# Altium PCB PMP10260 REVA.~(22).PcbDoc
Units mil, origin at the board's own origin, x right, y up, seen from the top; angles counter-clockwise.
Board outline 5118.11 x 4724.41 mil, 4 copper layers (Top Layer, MidLayer1, MidLayer2, Bottom Layer), stack 63.8 mil thick; 168 components, 80 nets, 422 pads, 195 vias.
Unrouted connection lines stored in the file: 320.
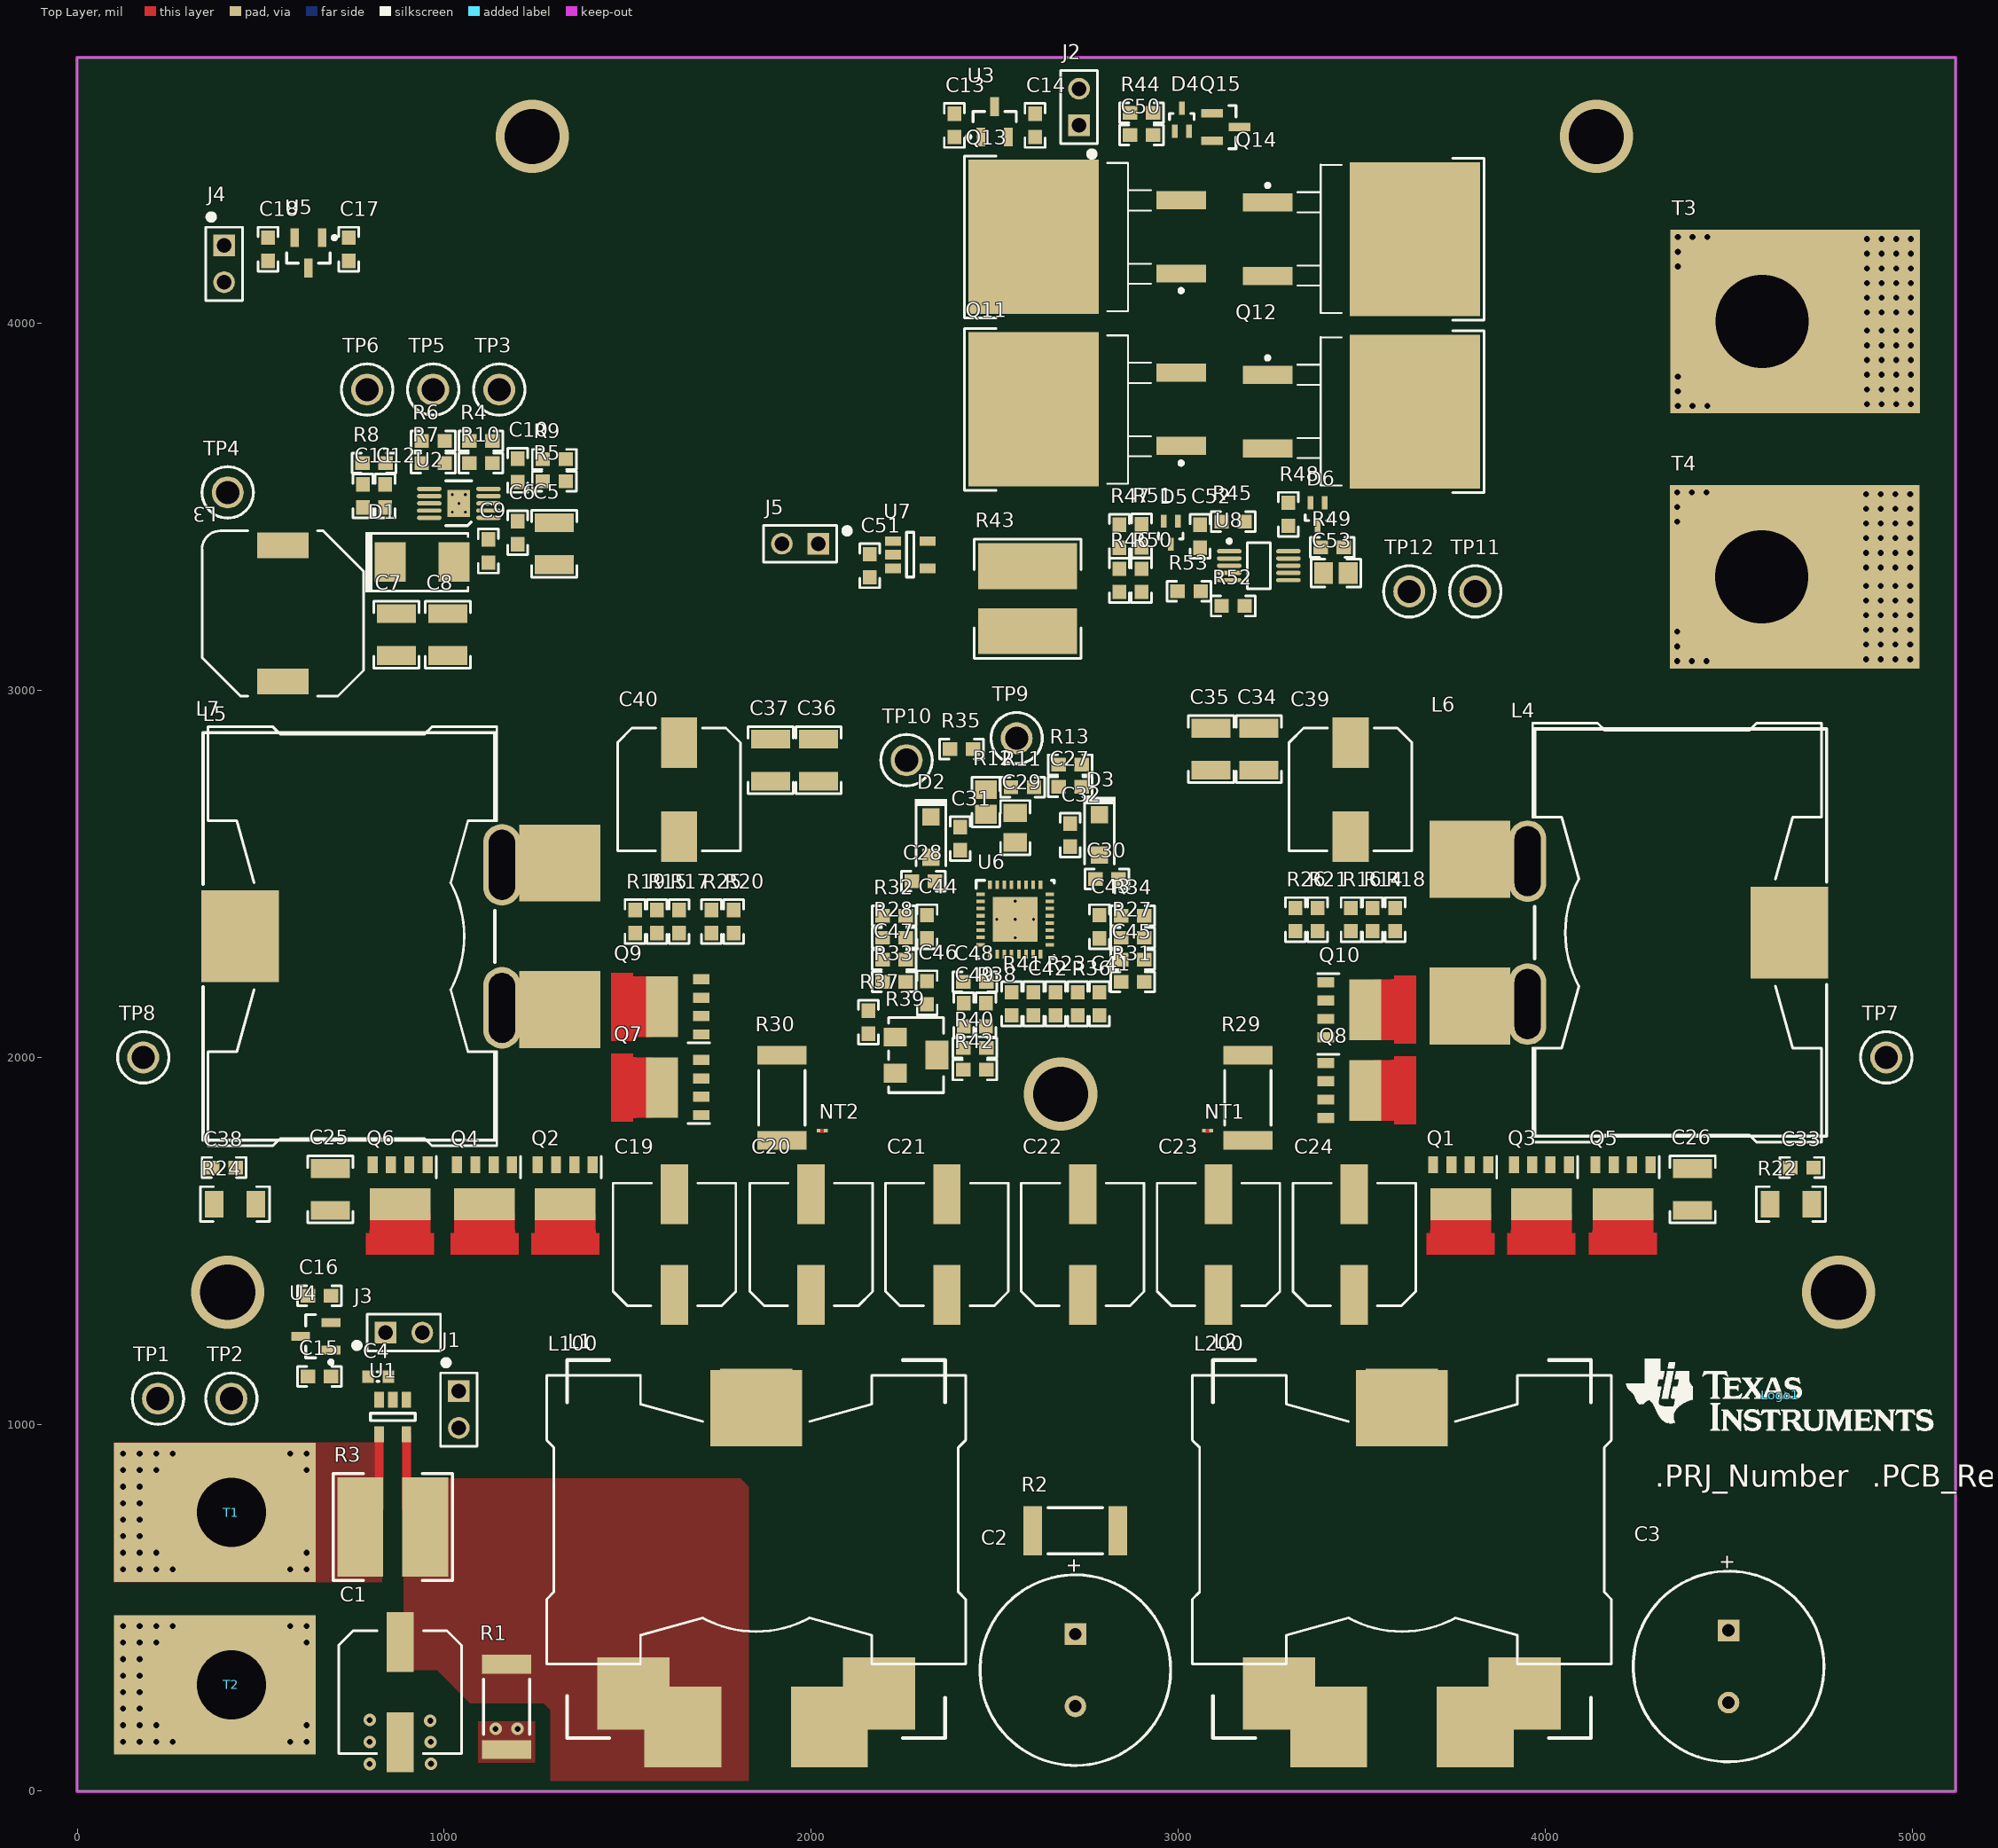
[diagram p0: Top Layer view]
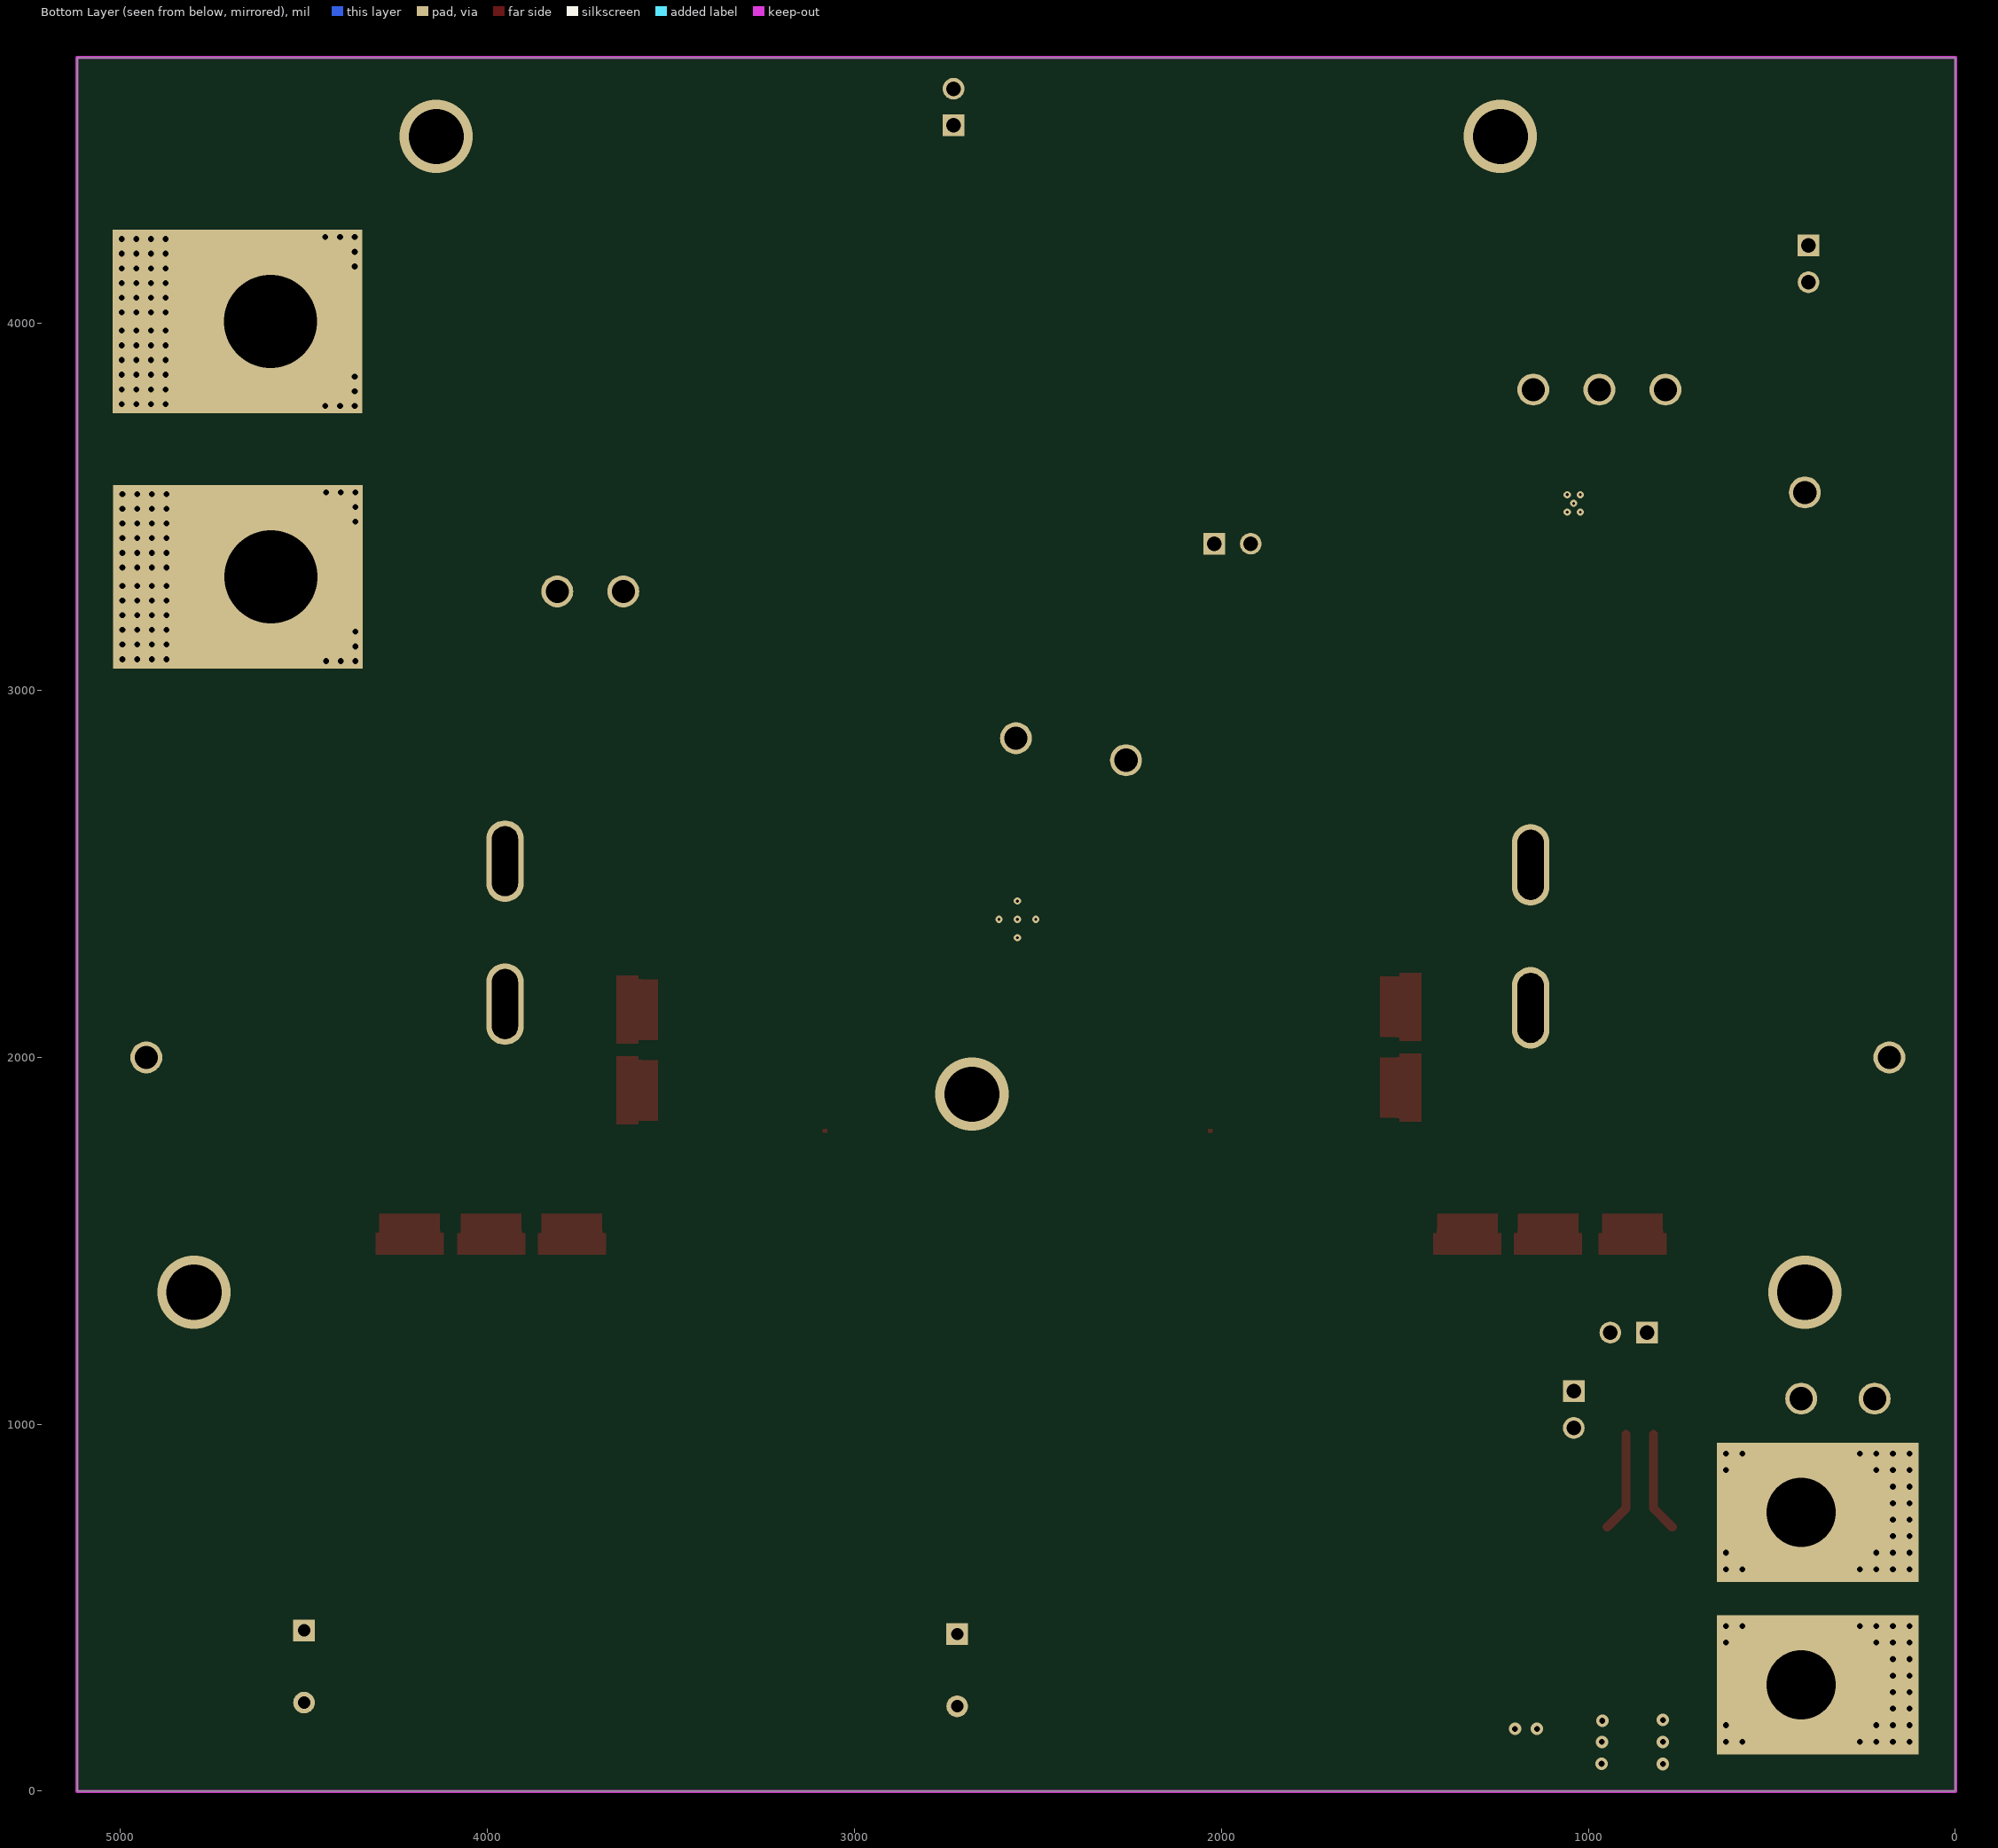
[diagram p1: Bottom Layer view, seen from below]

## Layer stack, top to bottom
Top Layer: signal copper 2.8
Dielectric: core 20, FR-4, Dk 4.8
MidLayer1: signal copper 2.8
Dielectric: prepreg 12.6, FR-4, Dk 4.8
MidLayer2: signal copper 2.8
Dielectric: core 20, FR-4, Dk 4.8
Bottom Layer: signal copper 2.8

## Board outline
0,0 5118.11,0 5118.11,4724.41 0,4724.41

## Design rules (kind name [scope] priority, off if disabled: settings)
AcuteAngle [All] p1: minimum=4.50000000000000E+0001 checktracksonly=FALSE
AssemblyTestPointUsage [All] p1: valid=2
Clearance Clearance_BoardEdge_MountingHoles [OnCopper and InComponentClass('Mounting Holes') vs IsKeepOut] p1: gap=40
Clearance Clearance_BoardEdge_Poly [OnCopper and InPoly vs IsKeepOut] p2: gap=25
Clearance Clearance_BoardEdge [OnCopper and Not InComponentClass('Logo') and not InComponentClass('FiducialMark') and not InRegion(1000,500,4000,800) and Not IsKeepout vs IsKeepOut] p3: gap=25
Clearance Clearance_Poly [InPolygon] p4: gap=15
Clearance [All] p5: gap=8
ComponentClearance ComponentClearance_Shunt [InComponentClass('Header') vs InComponentClass('Shunt')] p1: gap=0 collisioncheckmode=3 verticalgap=0 showdistances=FALSE
ComponentClearance ComponentClearance_Logo [InComponentClass('Logo')] p2: gap=20 collisioncheckmode=3 verticalgap=10 showdistances=FALSE
ComponentClearance ComponentClearance_ScrewToNut [(HasFootprint('NY PMS 440 0025 PH')) vs (HasFootprint('Keystone_1902C'))] p3: gap=5 collisioncheckmode=3 verticalgap=10 showdistances=FALSE
ComponentClearance ComponentClearance_MountingHoles [InComponentClass('Mounting Holes')] p4: gap=100 collisioncheckmode=3 verticalgap=100000 showdistances=FALSE
ComponentClearance ComponentClearance_SmallPassives [HasFootprint('0201*') or HasFootprint('0402*') or HasFootprint('0508') or HasFootprint('0603*') or HasFootprint('0612') or HasFootprint('0805*') or HasFootprint('0815*') or HasFootprint('0830*') or HasFootprint('1206*') or HasFootprint('1210*') or HasFootprint('1808*') or HasFootprint('1812*') or HasFootprint('1825*') or HasFootprint('2010*') or HasFootprint('2220*') or HasFootprint('2225*') or HasFootprint('2512*') or HasFootprint('2728*') or HasFootprint('3518*') vs HasFootprint('0201*') or HasFootprint('0402*') or HasFootprint('0508') or HasFootprint('0603*') or HasFootprint('0612') or HasFootprint('0805*') or HasFootprint('0815*') or HasFootprint('0830*') or HasFootprint('1206*') or HasFootprint('1210*') or HasFootprint('1808*') or HasFootprint('1812*') or HasFootprint('1825*') or HasFootprint('2010*') or HasFootprint('2220*') or HasFootprint('2225*') or HasFootprint('2512*') or HasFootprint('2728*') or HasFootprint('3518*')] p5: gap=15 collisioncheckmode=3 verticalgap=10 showdistances=FALSE
ComponentClearance ComponentClearance_THtoSMT [IsThruComponent vs IsSMTComponent] p6: gap=50 collisioncheckmode=3 verticalgap=30 showdistances=FALSE
ComponentClearance ComponentClearance_THtoTH [IsThruComponent vs IsThruComponent] p7: gap=50 collisioncheckmode=3 verticalgap=30 showdistances=FALSE
ComponentClearance [All] p8: gap=25 collisioncheckmode=3 verticalgap=10 showdistances=FALSE
DiffPairsRouting [All] p1: maxlimit=100 minlimit=10 mostfreqgap=10 maxuncoupledlength=1000
FabricationTestPointUsage TestPointUsage [All] p1: valid=2 allowmultiple=FALSE
FabricationTestpoint Testpoint [All] p1: side=3 testpointundercomponent=TRUE minsize=40 maxsize=100 preferedsize=60 minholesize=0 maxholesize=40 preferedholesize=32 testpointgrid=1 allowsidetop=TRUE allowsidebottom=TRUE usegrid=TRUE gridtolerance=0.01
FanoutControl Fanout_LCC [IsLCC] p1: bgadir=Out bgaviamode=Centered fanoutstyle=Auto fanoutdirection=Alternating viagrid=1 // Fanout_LCC (Default Rule)
FanoutControl Fanout_BGA [IsBGA] p2: bgadir=Out bgaviamode=Centered fanoutstyle=Auto fanoutdirection=Alternating viagrid=1 // Fanout_BGA (Default Rule)
FanoutControl Fanout_Default [All] p4: bgadir=Out bgaviamode=Centered fanoutstyle=Auto fanoutdirection=Alternating viagrid=1 // Fanout_Default (Default Rule)
FanoutControl Fanout_Small [(CompPinCount < 5)] p5: bgadir=Out bgaviamode=Centered fanoutstyle=Auto fanoutdirection=OutThenIn viagrid=1 // Fanout_Small (Default Rule)
HoleSize [All] p1: absolutevalues=TRUE maxlimit=251 minlimit=8 maxpercent=80.000 minpercent=20.000
MinimumAnnularRing MinimumAnnularRing_ThermalPadVias [IsVia and InAnyComponent] p1: minimumring=5.91
MinimumAnnularRing [All] p2: minimumring=9
MinimumSolderMaskSliver MinimumSolderMaskSliver_Logo [InComponentClass('Logo') vs InComponentClass('Logo')] p1: minsoldermaskwidth=0.7
MinimumSolderMaskSliver [All] p2: minsoldermaskwidth=3
PlaneClearance [All] p1: clearance=15
PlaneConnect [All] p1: planeconnectstyle=Direct reliefexpansion=10 reliefentries=4 reliefconductorwidth=10 reliefairgap=10
PolygonConnect [All] p1: connectstyle=Direct reliefconductorwidth=10 reliefentries=4 polygonreliefangle="90 Angle" airgapwidth=10
RoomDefinition "PMP10260 REVA SH3" [InComponentClass('PMP10260 REVA SH3')] p1: confinementstyle=ConfineIn formatcopy=TRUE lockcomponents=FALSE outline -692,-1534 1308,-1534 1308,-534 -692,-534
RoomDefinition "PMP10260 REVA SH2" [InComponentClass('PMP10260 REVA SH2')] p2: confinementstyle=ConfineIn formatcopy=TRUE lockcomponents=FALSE outline -692,-1534 1308,-1534 1308,-534 -692,-534
RoutingVias ThermalPadVias [IsVia and InAnyComponent] p1: holewidth=7.87 width=19.68 viastyle="Through Hole" minholewidth=7.87 minwidth=19.68 maxholewidth=12.99 maxwidth=23.62
RoutingVias [All] p2: holewidth=16 width=34 viastyle="Through Hole" minholewidth=7.87 minwidth=26 maxholewidth=40 maxwidth=65
SMDToCorner [All] p1: distance=30000
SilkToSilkClearance [All] p1: silktosilkclearance=0
SilkscreenOverComponentPads [All] p1: minsilkscreentomaskgap=0
SolderMaskExpansion [All] p1: expansion=1.97
Width [All] p1: maxlimit=100 minlimit=6 preferedwidth=10 checkconnectedcopper=TRUE
13 further rules are at their usual default settings.

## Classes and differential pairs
component class Logo: Logo1
component class Header: J1 J2 J3 J4 J5
component class "PMP10260 REVA SH1": C1 C2 C3 C4 C5 C6 C7 C8 C9 C10 C11 C12 C13 C14 C15 C16 C17 C18 D1 J1 J2 J3 J4 L1 L2 L3 L100 L200 Logo1 R1 R2 R3 R4 R5 R6 R7 R8 R9 R10 T1 T2 TP1 TP2 TP3 TP4 TP5 TP6 U1 U2 U3 U4 U5
component class "PMP10260 REVA SH2": C19 C20 C21 C22 C23 C24 C25 C26 C27 C28 C29 C30 C31 C32 C33 C34 C35 C36 C37 C38 C39 C40 C41 C42 C43 C44 C45 C46 C47 C48 C49 D2 D3 L4 L5 L6 L7 NT1 NT2 Q1 Q2 Q3 Q4 Q5 Q6 Q7 Q8 Q9 Q10 R11 R12 R13 R14 R15 R16 R17 R18 R19 R20 R21 R22 R23 R24 R25 R26 R27 R28 R29 R30 R31 R32 R33 R34 R35 R36 R37 R38 R39 R40 R41 R42 TP7 TP8 TP9 TP10 U6
component class "PMP10260 REVA SH3": C50 C51 C52 C53 D4 D5 D6 J5 Q11 Q12 Q13 Q14 Q15 R43 R44 R45 R46 R47 R48 R49 R50 R51 R52 R53 T3 T4 TP11 TP12 U7 U8

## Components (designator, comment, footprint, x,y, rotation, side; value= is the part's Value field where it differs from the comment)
C1 "63SXV33M" SXV_E12 880,270 r270 top
C2 "63ZLH470M12.5X25" ZLH_1250x2500 2720,330 r270 top
C3 "63ZLH470M12.5X25" ZLH_1250x2500 4500,340 r270 top
C4 "C1608X7R1H104K" 0603L 820,1130 r0 top
C5 "GRM32ER72A225KA35L" 1210 1300.02,3399.97 r270 top
C6 "GRM188R72A104KA35D" 0603 1200.02,3429.97 r270 top
C7 "C3225X7R1C226M" 1210 869.7,3152.41 r90 top
C8 "C3225X7R1C226M" 1210 1009.7,3152.41 r90 top
C9 "C1608X7R1H104K" 0603 1120.02,3379.97 r90 top
C10 "C1608X7R1H103K" 0603 1200.02,3599.97 r90 top
C11 "C1608C0G1H472J" 0603 778.56,3529.97 r270 top
C12 "" 0603 838.56,3529.97 r270 top
C13 "C1608X7R1H104K" 0603 2390,4540 r90 top
C14 "C1608X7R1E105K080AB" 0603 2610,4540 r90 top
C15 "C1608X7R1H104K" 0603 660,1130 r180 top
C16 "C1608X7R1E105K080AB" 0603 660,1350 r180 top
C17 "C1608X7R1H104K" 0603 740,4202.44 r270 top
C18 "C1608X7R1E105K080AB" 0603 520,4202.44 r270 top
C19 "63SXV33M" SXV_E12 1627.32,1490 r90 top
C20 "63SXV33M" SXV_E12 2000,1490 r90 top
C21 "63SXV33M" SXV_E12 2370,1490 r90 top
C22 "63SXV33M" SXV_E12 2740,1490 r90 top
C23 "63SXV33M" SXV_E12 3110,1490 r90 top
C24 "63SXV33M" SXV_E12 3480,1490 r90 top
C25 "GRM32ER72A225KA35L" 1210 690,1640 r90 top
C26 "GRM32ER72A225KA35L" 1210 4402.28,1640.16 r90 top
C27 "C1608C0G1H471J" 0603 2706.06,2737.36 r0 top
C28 "C1608X7R1E105K080AB" 0603 2306.06,2480.51 r180 top
C29 "C2012X7R2A104K" 0805_HV 2556.06,2626.06 r90 top
C30 "C1608X7R1E105K080AB" 0603 2806.06,2486.06 r0 top
C31 "C1608X7R1E105K080AB" 0603 2406.06,2596.06 r270 top
C32 "C1608X7R1E105K080AB" 0603 2706.06,2606.06 r270 top
C33 "C0603C222K5RAC" 0603 4700,1700 r0 top
C34 "GMK325AB7106MM-T" 1210 3220,2840 r270 top
C35 "" 1210 3090,2840 r270 top
C36 "" 1210 2020,2810 r270 top
C37 "GMK325AB7106MM-T" 1210 1890,2810 r270 top
C38 "C0603C222K5RAC" 0603 400,1700 r180 top
C39 "20SVPF390M" SM_RADIAL_8MM 3470,2730 r270 top
C40 "20SVPF390M" SM_RADIAL_8MM 1640,2730 r270 top
C41 "C1608X7R1H104K" 0603 2786.06,2146.06 r90 top
C42 "C0603C474K4RACTU" 0603 2606.06,2146.06 r90 top
C43 "C1608C0G1H102J" 0603 2786.06,2356.06 r90 top
C44 "C1608C0G1H102J" 0603 2316.06,2356.06 r90 top
C45 "C1608C0G1H102J" 0603 2876.06,2266.06 r0 top
C46 "C1608X7R1H104K" 0603 2316.06,2176.06 r270 top
C47 "C1608C0G1H102J" 0603 2226.06,2266.06 r180 top
C48 "C1608C0G1H101J" 0603 2446.06,2206.06 r180 top
C49 "GRM188R71H333KA61D" 0603 2416.06,2116.06 r90 top
C50 "C1608X7R1H103K" 0603 2900.2,4514.07 r180 top
C51 "C1608X7R1H104K" 0603 2160,3340 r90 top
C52 "C1608X7R1H104K" 0603 3060,3420 r90 top
C53 "0805YC274KAT2A" 0805 3430,3320 r0 top
D1 "MBRS1100T3G" SMB 940.02,3349.97 r0 top
D2 "PMEG6010CEH" SOD-123F 2326.06,2600.51 r270 top
D3 "PMEG6010CEH" SOD-123F 2786.06,2606.06 r270 top
D4 "BAS116T-7-F" SOT-523 3010.2,4555.39 r90 top
D5 "BAS116T-7-F" SOT-523 2980,3430 r270 top
D6 "BAS116T-7-F" SOT-523 3380,3480 r270 top
J1 "PEC02SAAN" CONN_PEC02SAAN 1040,1040 r270 top
J2 "PEC02SAAN" CONN_PEC02SAAN 2730,4590 r90 top
J3 "PEC02SAAN" CONN_PEC02SAAN 890,1250 r0 top
J4 "PEC02SAAN" CONN_PEC02SAAN 400,4162.44 r270 top
J5 "PEC02SAAN" CONN_PEC02SAAN 1970,3400 r180 top
L1 "PG1096.152NL" IND_PG1096 1850,660 r0 top
L2 "PG1096.152NL" IND_PG1096 3610,660 r0 top
L3 "MSS1048-104MLB" MSS1048 560.02,3209.97 r270 top
L4 "" SER29XX 4330,2340 r90 top
L5 "" SER29XX 779.84,2330 r270 top
L6 "SER2915H-682KL" SER2915 4360,2340 r0 top
L7 "SER2915H-682KL" SER2915 749.84,2330 r180 top
L100 "" SER2918 1850,740 r90 top
L200 "" SER2918 3610,740 r90 top
Logo1 "Texas Instruments" TI_Stacked_Overlay_Small 4640,1080 r0 top
NT1 "Net-Tie" Net-Tie_10mil 3080,1800 r0 top net-tie
NT2 "Net-Tie" Net-Tie_10mil 2030,1800 r0 top net-tie
Q1 "BUK7Y6R0-60EX" LFPAK56 3770,1600 r180 top
Q2 "BUK7Y6R0-60EX" LFPAK56 1329.84,1600 r180 top
Q3 "BUK7Y6R0-60EX" LFPAK56 3990,1600 r180 top
Q4 "BUK7Y6R0-60EX" LFPAK56 1109.84,1600 r180 top
Q5 "BUK7Y6R0-60EX" LFPAK56 4212.28,1600.16 r180 top
Q6 "BUK7Y6R0-60EX" LFPAK56 879.84,1600 r180 top
Q7 "BUK7Y6R0-60EX" LFPAK56 1593.46,1917.72 r90 top
Q8 "BUK7Y6R0-60EX" LFPAK56 3510,1910 r270 top
Q9 "BUK7Y6R0-60EX" LFPAK56 1593.46,2137.72 r90 top
Q10 "BUK7Y6R0-60EX" LFPAK56 3510,2130 r270 top
Q11 "IPB120N04S4-02" DDPAK 2762.09,3766.18 r180 top
Q12 "IPB120N04S4-02" DDPAK 3490,3760 r0 top
Q13 "IPB120N04S4-02" DDPAK 2762.09,4236.18 r180 top
Q14 "IPB120N04S4-02" DDPAK 3490,4230 r0 top
Q15 "MMBT2222A" SOT-23 3130.2,4535.39 r0 top
R1 "CSRN2512FKR200" 2512 1170,230 r270 top
R2 "CSRN2512FKR200" 2512 2720,710 r0 top
R3 "CSS2725FT1L00" CSS2725_0005 860,720 r0 top
R4 "CRCW060349R9FKEA" 0603 1100,3680 r0 top
R5 "CRCW0603178KFKEA" 0603 1300.02,3569.97 r0 top
R6 "CRCW060353K6FKEA" 0603 970.02,3679.65 r0 top
R7 "CRCW060310K2FKEA" 0603 970.02,3619.97 r180 top
R8 "CRCW060388K7FKEA" 0603 808.56,3619.97 r180 top
R9 "CRCW060349K9FKEA" 0603 1300.02,3629.97 r180 top
R10 "CRCW0603237KFKEA" 0603 1100.02,3619.97 r0 top
R11 "CRCW060375K0FKEA" 0603 2576.06,2736.06 r180 top
R12 "CRCW08051R00FKEA" 0805 2476.06,2696.06 r270 top
R13 "CRCW06035K76FKEA" 0603 2706.06,2797.36 r180 top
R14 "CRCW06032R20JNEA" 0603 3530,2375.55 r270 top
R15 "CRCW06032R20JNEA" 0603 1580,2370 r90 top
R16 "CRCW06032R20JNEA" 0603 3471.3,2375.55 r270 top
R17 "CRCW06032R20JNEA" 0603 1640,2370 r90 top
R18 "CRCW06032R20JNEA" 0603 3591.3,2375.55 r270 top
R19 "CRCW06032R20JNEA" 0603 1520,2370 r90 top
R20 "CRCW06032R20JNEA" 0603 1788.7,2370 r90 top
R21 "CRCW06032R20JNEA" 0603 3380,2375.55 r270 top
R22 "CRCW120610R0JNEA" 1206 4670,1600 r0 top
R23 "CRCW06030000Z0EA" 0603 2666.06,2146.06 r270 top
R24 "CRCW120610R0JNEA" 1206 430,1600 r180 top
R25 "CRCW06032R20JNEA" 0603 1728.7,2370 r90 top
R26 "CRCW06032R20JNEA" 0603 3320,2375.55 r270 top
R27 "RC0603FR-07100RL" 0603 2876.06,2326.06 r0 top
R28 "RC0603FR-07100RL" 0603 2226.06,2326.06 r180 top
R29 "ERJ-M1WTF1M0U" 2512 3190,1890 r90 top
R30 "ERJ-M1WTF1M0U" 2512 1920,1890 r90 top
R31 "CRCW0603249KFKEA" 0603 2876.06,2206.06 r0 top
R32 "RC0603FR-07100RL" 0603 2226.06,2386.06 r180 top
R33 "CRCW0603249KFKEA" 0603 2226.06,2206.06 r180 top
R34 "RC0603FR-07100RL" 0603 2876.06,2386.06 r0 top
R35 "CRCW060349R9FKEA" 0603 2410,2840 r0 top
R36 "CRCW06030000Z0EA" 0603 2726.06,2146.06 r90 top
R37 "CRCW060320K0FKEA" 0603 2156.06,2096.06 r90 top
R38 "CRCW060320K0FKEA" 0603 2476.06,2116.06 r270 top
R39 "3224W-2-103E" TRIM_3224W 2286.06,2006.06 r0 top
R40 "CRCW06031K62FKEA" 0603 2446.06,2026.06 r180 top
R41 "CRCW060336K5FKEA" 0603 2546.06,2146.06 r90 top
R42 "CRCW06033K01FKEA" 0603 2446.06,1966.06 r180 top
R43 "CSS2725FTL500" CSS2725_0005 2590,3250 r90 top
R44 "CRCW060310K0FKEA" 0603 2900.2,4574.07 r0 top
R45 "CRCW060313K7FKEA" 0603 3150,3460 r180 top
R46 "CRCW060382K5FKEA" 0603 2840,3300 r270 top
R47 "CRCW060382K5FKEA" 0603 2840,3420.47 r90 top
R48 "CRCW06031K00FKEA" 0603 3300,3480 r270 top
R49 "CRCW060310K0FKEA" 0603 3420,3390 r180 top
R50 "CRCW060316K5FKEA" 0603 2900,3300 r90 top
R51 "CRCW060311K0FKEA" 0603 2900,3421.5 r270 top
R52 "CRCW060310K0FKEA" 0603 3150,3230 r0 top
R53 "CRCW060310K0FKEA" 0603 3030,3270 r0 top
T1 "CB35-36-CY" CB35-36-CY 420,760 r0 top
T2 "CB35-36-CY" CB35-36-CY 420,290 r0 top
T3 "CB70-14-CY" CB70-14-CY 4591.89,4005.55 r180 top
T4 "CB70-14-CY" CB70-14-CY 4590,3310 r180 top
TP1 "5010" Keystone5010 220,1070 r180 top
TP2 "5011" Keystone5011 420,1070 r180 top
TP3 "5010" Keystone5010 1150,3820 r180 top
TP4 "5010" Keystone5010 410.02,3539.65 r180 top
TP5 "5010" Keystone5010 970,3820 r180 top
TP6 "5011" Keystone5011 790,3820 r180 top
TP7 "5010" Keystone5010 4930,2000 r0 top
TP8 "5010" Keystone5010 180,2000 r0 top
TP9 "5010" Keystone5010 2560,2870 r0 top
TP10 "5010" Keystone5010 2260,2810 r0 top
TP11 "5010" Keystone5010 3810,3270 r0 top
TP12 "5010" Keystone5010 3630,3270 r0 top
U1 "INA198AIDBV" DBV0005A_N 860,1020 r270 top
U2 "TPS54060DGQ" DGQ0010D_N 1040.02,3509.97 r180 top
U3 "LM50CIM3/NOPB" MF03A_N 2500,4550 r90 top
U4 "LM50CIM3/NOPB" MF03A_N 650,1240 r180 top
U5 "LM50CIM3/NOPB" MF03A_N 630,4192.44 r270 top
U6 "LM5119PSQ/NOPB" RTV0032A 2556.06,2376.06 r0 top
U7 "INA198AIDBV" DBV0005A_N 2270,3370 r0 top
U8 "LM5060Q1MM/NOPB" MUB10A_N 3220,3340 r0 top

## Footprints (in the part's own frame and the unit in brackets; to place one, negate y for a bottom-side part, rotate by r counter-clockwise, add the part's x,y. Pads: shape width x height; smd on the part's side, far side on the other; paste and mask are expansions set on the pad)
0603 [mm] "0603 from SM-752 data"
  rect 1x0.95 smd: 1(-0.8,0) 2(0.8,0)
  silkscreen extent -1.52,-0.69 1.52,0.69, body extent -0.87,-0.47 0.87,0.47, height 0.85
0603L [mm] "0603 from SM-752 data"
  rect 0.8x0.85 smd: 1(-0.7,0) 2(0.7,0)
  silkscreen extent -0.07,-0.33 0.07,0.33, body extent -0.87,-0.47 0.87,0.47, height 0.85
0805 [mm] "0805 from SM-752 data"
  rect 1.3x1.5 smd: 1(-0.85,0) 2(0.85,0)
  silkscreen extent -1.72,-0.97 1.72,0.97, body extent -1.1,-0.72 1.1,0.72, height 1.1
0805_HV [mil] "0805 with 30mil clearance between pads"
  rect 50x63 smd: 1(-40,0) 2(40,0)
  silkscreen extent -74,-40 74,40, body extent -43,-29 43,29, height 43
1206 [mm] "1206 from SM-752 data"
  rect 1.3x1.85 smd: 1(-1.45,0) 2(1.45,0)
  silkscreen extent -2.4,-1.21 2.4,1.21, body extent -1.7,-0.9 1.7,0.9, height 1.35
1210 [mm] "1210 from SM-752 data"
  rect 1.3x2.7 smd: 1(-1.45,0) 2(1.45,0)
  silkscreen extent -2.32,-1.57 2.32,1.57, body extent -1.7,-1.35 1.7,1.35, height 1.35
2512 [mm] "Chip Resistor, Body 6.3x3.2mm, IPC Medium Density"
  rect 1.3x3.4 smd: 1(-2.95,0) 2(2.95,0)
  silkscreen extent -1.9,-1.6 1.9,1.6, body extent -3.22,-1.67 3.22,1.67, height 0.71
CB35-36-CY [mil] "Terminal 50A Lug"
  rect 550x380 hole 188 copper offset -45,0 paste-190: 1(0,0)
  body extent -960,-189 230,191, height 614
CB70-14-CY [mil] "Terminal 90A Lug"
  rect 680x500 hole 254 copper offset -90,0 paste-250: 1(0,0)
  body extent -1300,-260 250,260, height 714
CONN_PEC02SAAN [mm] "SULLINS"
  rect 1.5x1.5 hole 1.016: 1(-1.27,0)
  round 1.5 hole 1.016: 2(1.27,0)
  silkscreen extent -3.45,-1.27 2.54,1.27, body extent -2.54,-1.27 2.54,1.27, height 8.38
CSS2725_0005 [mm] "STACKPOLE ELECTRONICS"
  rect 3.18x6.86 smd: 1(-2.25,0) 2(2.25,0)
  silkscreen extent -4.13,-3.7 4.13,3.7, body extent -3.53,-3.35 3.53,3.35, height 1.24
DBV0005A_N [mm] "SOT23, 5-Leads, Body 2.9x1.6mm, Pitch 0.95mm, Lead Span 2.8mm, IPC Medium Density"
  rect 1.1x0.65 smd: 1(-1.2,0.95) 2(-1.2,0) 3(-1.2,-0.95) 4(1.2,-0.95) 5(1.2,0.95)
  silkscreen extent -0.25,-1.55 0.25,1.55, body extent -1.42,-1.46 1.42,1.46, height 1.08
DDPAK [mil] "D2-PAK, 3-Pads, Body 9.7x10.4mm (max), TO-263AB, using Vishay Silionix recommended pad sizes"
  rect 135x49.49 smd: 1(-246.06,100) 3(-246.06,-100)
  rect 355x420 smd paste-181.1: 4(155.51,0)
  silkscreen extent -251,-220 344,220, body extent -295,-202 324,202, height 180
DGQ0010D_N [mm] "TSSOP, 10-Leads, Body 3x3mm, Pitch 0.5mm, Thermal Pad 1.88x1.57mm, IPC Medium Density"
  oval 1.7x0.3 smd: 1(-2.05,1) 2(-2.05,0.5) 3(-2.05,0) 4(-2.05,-0.5) 5(-2.05,-1) 6(2.05,-1) 7(2.05,-0.5) 8(2.05,0) 9(2.05,0.5) 10(2.05,1)
  rect 1.57x1.88 smd: 11(0,0)
  silkscreen extent -0.9,-1.55 0.9,1.55, body extent -1.55,-1.55 1.55,1.55, height 1.1
IND_PG1096 [mm] "PULSE"
  rect 5x5 smd: 1(-8.5,-10) 2(8.5,-10) 3(0,10)
  silkscreen extent -13.08,-13.08 13.08,13.08, body extent -13,-13 13,13, height 14.51
Keystone5010 [mil] "Keystone Multipurpose loops"
  round 87 hole 63: 1(0,0)
  silkscreen extent -70,-70 70,70, body extent -63,-63 63,62, height 319
Keystone5011 [mil] "Keystone Multipurpose loops"
  round 87 hole 63: 1(0,0)
  silkscreen extent -70,-70 70,70, body extent -63,-63 63,62, height 319
LFPAK56 [mm] "NXP Semiconductor"
  rect 0.7x1.15 smd paste-0.05: 1(-1.905,-2.725) 2(-0.635,-2.725) 3(0.635,-2.725) 4(1.905,-2.725)
  rect 4.2x2.2 smd paste-1.52: 5(0,0)
  Top Layer region: -2.1,0.65 2.1,0.65 2.1,2 -2.1,2
  Top Layer region: -2.1,1.8 -2.1,2 -2.35,2 -2.35,3.5 2.35,3.5 2.35,2 2.1,2 2.1,1.8
  silkscreen extent -2.5,-3.3 -2.5,-1.8, body extent -2.43,-3.14 2.47,3.29, height 1.18
MF03A_N [mm] "SOT23, 3-Leads, Body 2.9x1.3mm, Pitch 0.95mm, Lead Span 2.4mm, IPC Medium Density"
  rect 1.3x0.6 smd: 1(-1.05,0.95) 2(-1.05,-0.95) 3(1.05,0)
  silkscreen extent -1.17,-1.5 0.7,1.92, body extent -0.7,-1.5 0.7,1.5, height 1.12
MSS1048 [mm] "Coilcraft recommended land pattern Document 462-2 Revised 06/09/09"
  rect 1.78x3.56 smd: 1(-4.7,0) 2(4.7,0)
  silkscreen extent -5.72,-5.59 5.72,5.59, body extent -5.15,-5.1 5.15,5.1, height 5.12
MUB10A_N [mm] "TSSOP, 10-Leads, Body 3x3mm, Pitch 0.5mm, IPC Medium Density"
  oval 1.7x0.3 smd: 1(-2.05,1) 2(-2.05,0.5) 3(-2.05,0) 4(-2.05,-0.5) 5(-2.05,-1) 6(2.05,-1) 7(2.05,-0.5) 8(2.05,0) 9(2.05,0.5) 10(2.05,1)
  silkscreen extent -2.17,-1.6 0.8,1.82, body extent -1.6,-1.6 1.6,1.6, height 1.09
Net-Tie_10mil [mil] "10mil net tie, no solder mask opening, no solder paste"
  rect 10x10 smd paste-5 mask-5: 1(-10,0) 2(10,0)
  Top Layer region: -6,5 6,5 6,-5 -6,-5
RTV0032A [mm] "QFN, 32-Leads, Body 5x5mm, Pitch 0.5mm"
  rect 0.6x0.25 smd: 1(-2.4,1.75) 2(-2.4,1.25) 3(-2.4,0.75) 4(-2.4,0.25) 5(-2.4,-0.25) 6(-2.4,-0.75) 7(-2.4,-1.25) 8(-2.4,-1.75) 17(2.4,-1.75) 18(2.4,-1.25) 19(2.4,-0.75) 20(2.4,-0.25) 21(2.4,0.25) 22(2.4,0.75) 23(2.4,1.25) 24(2.4,1.75)
  rect 0.25x0.6 smd: 9(-1.75,-2.4) 10(-1.25,-2.4) 11(-0.75,-2.4) 12(-0.25,-2.4) 13(0.25,-2.4) 14(0.75,-2.4) 15(1.25,-2.4) 16(1.75,-2.4) 25(1.75,2.4) 26(1.25,2.4) 27(0.75,2.4) 28(0.25,2.4) 29(-0.25,2.4) 30(-0.75,2.4) 31(-1.25,2.4) 32(-1.75,2.4)
  rect 3.1x3.1 smd paste-1.55: 33(0,0)
  silkscreen extent -2.7,-2.7 2.7,2.7, body extent -2.55,-2.55 2.55,2.55, height 0.81
SER29XX [mm] "COILCRAFT"
  oval 5.65x2.6 hole 1.8 slot 4.85 at 0 deg: 1(-4.95,9.59) 2(4.95,9.59)
  rect 6.35x5.28 smd: 3(0,-8.59)
  silkscreen extent -14.1,-11.1 14.1,9.1, body extent -14,-11 14,10.39, height 20
SER2915 [mm] "Coilcraft recommended land pattern.  Document 644-2, rev 12/12/08"
  rect 5.59x5.33 smd: 1(-14.355,5.075) 2(-14.355,-5.075)
  rect 5.28x6.35 smd: 3(7.72,0)
  silkscreen extent -10,-14.5 10,14.5, body extent -16.8,-13.95 11.03,13.95, height 15.36
SER2918 [mm] "Coilcraft recommended land pattern.  Document 644-2, rev 12/12/08"
  rect 5.59x5.33 smd: 1(-14.355,5.075) 2(-14.355,-5.075)
  rect 5.28x6.35 smd: 3(7.72,0)
  silkscreen extent -10,-14.5 10,14.5, body extent -16.8,-13.95 11.03,13.95, height 17.78
SM_RADIAL_8MM [mm] "Nichicon 8x10"
  rect 3.5x2.5 smd: 1(-3.25,0) 2(3.25,0)
  silkscreen extent -4.25,-4.25 4.25,4.25, body extent -4.26,-4.26 4.26,4.26, height 10.5
SMB [mil] "Molded Diode, 2-Leads, Body 5.4x3.6mm, IPC Medium Density, based on OnSemi component dimensions"
  rect 85x107.99 smd: 1(-87.01,0) 2(87.01,0)
  silkscreen extent -155,-82 125,82, body extent -106,-71 106,71, height 91
SOD-123F [mm] "NXP recommended land pattern"
  rect 1.2x1.2 smd paste-0.05: 1(-1.4,0) 2(1.4,0)
  silkscreen extent -2.64,-1.12 2.01,1.12, body extent -1.8,-0.85 1.8,0.85, height 1.2
SOT-23 [mm] "SOT23, 3-Leads, Body 2.9x1.3mm, Pitch 0.95mm, Lead Span 2.5mm, IPC Medium Density"
  rect 1.5x0.6 smd: 1(-0.95,0.95) 2(-0.95,-0.95) 3(0.95,0)
  silkscreen extent 0.2,-1.5 0.7,1.5, body extent -1.16,-1.45 1.21,1.45, height 1
SOT-523 [mm] "From Diodes Inc datasheet component parameters"
  rect 0.9x0.4 smd: 1(-0.8,0.5) 2(-0.8,-0.5) 3(0.8,0)
  silkscreen extent 0.02,-0.85 0.42,0.85, body extent -0.8,-0.8 0.8,0.8, height 0.79
SXV_E12 [mm] "OS-CON  8x10"
  rect 4.15x1.9 smd: 1(-3.475,0) 2(3.475,0)
  silkscreen extent -4.25,-4.25 4.25,4.25, body extent -4.26,-4.26 4.26,4.26, height 12
TI_Stacked_Overlay_Small [mil]
  silkscreen extent -418,-98 418,98
TRIM_3224W [mm] "BOURNS"
  rect 1.6x1.3 smd: 1(-1.45,1.25) 3(-1.45,-1.25)
  rect 1.6x2 smd: 2(1.45,0)
  silkscreen extent -1.9,-2.6 1.9,2.6, body extent -1.8,-2.5 1.8,2.5, height 5.31
ZLH_1250x2500 [mm] "Rubycon"
  rect 1.5x1.5 hole 0.85: 1(-2.5,0)
  round 1.5 hole 0.85: 2(2.5,0)
  silkscreen extent -6.6,-6.6 6.6,6.6, body extent -6.45,-6.49 6.49,6.49, height 26.51

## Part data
C1 C19 C20 C21 C22 C23 C24: "CAP, OS-CON, 33uF, 63V, +/-20%, 0.025 ohm, 8.0x11.9mm SMD"
C2 C3: "CAP, AL, 470uF, 63V, +/-20%, 0.043 ohm, TH"
C4 C9 C13 C15 C17 C41 C46 C51 C52: "CAP, CERM, 0.1uF, 50V, +/-10%, X7R, 0603"
C5 C25 C26: "CAP, CERM, 2.2uF, 100V, +/-10%, X7R, 1210"
C6: "CAP, CERM, 0.1uF, 100V, +/-10%, X7R, 0603"
C7 C8: "CAP, CERM, 22uF, 16V, +/-20%, X7R, 1210"
C10 C50: "CAP, CERM, 0.01uF, 50V, +/-10%, X7R, 0603"
C11: library part C1608C0G1H332J, "CAP, CERM, 4700pF, 50V, +/-5%, C0G/NP0, 0603"
C12: library part C1608X7R1H104K, "CAP, open, 0603"
C14 C16 C18 C28 C30 C31 C32: "CAP, CERM, 1uF, 25V, +/-10%, X7R, 0603"
C27: "CAP, CERM, 470pF, 50V, +/-5%, C0G/NP0, 0603"
C29: "CAP, CERM, 0.1uF, 100V, +/-10%, X7R, 0805"
C33 C38: "CAP, CERM, 2200pF, 50V, +/-10%, X7R, 0603"
C34 C37: "CAP, CERM, 10uF, 35V, +/-20%, X7R, 1206"
C35 C36: library part C3225X7R1H335M, "CAP, CERM, open, 1210"
C39 C40: library part 20SVP100M, "CAP, OS-CON, 390uF, 20V, +/-20%, 0.014 ohm, 8x10 SMD"
C42: "CAP, CERM, 0.47uF, 16V, +/-10%, X7R, 0603"
C43 C44 C45 C47: "CAP, CERM, 1000pF, 50V, +/-5%, C0G/NP0, 0603"
C48: "CAP, CERM, 100pF, 50V, +/-5%, C0G/NP0, 0603"
C49: "CAP, CERM, 0.033uF, 50V, +/-10%, X7R, 0603"
C53: "CAP, CERM, 0.27uF, 16V, +/-10%, X7R, 0805"
D1: "Diode, Schottky, 100V, 1A, SMB"
D2 D3: library part PMEG6010CEH,115, "Diode, Schottky, 60V, 1A, SOD-123F"
D4 D5 D6: "Diode, Switching, 85V, 0.215A, SOT-523"
J1 J2 J3 J4 J5: "Header, 100mil, 2x1, Tin, TH"
L1 L2: library part PG1096.252NL, "Inductor, Shielded E Core, Ferrite, 1.5uH, 47A, 0.00085 ohm, SMD"
L3: "Inductor, Shielded Drum Core, Ferrite, 100uH, 1.36A, 0.25 ohm, SMD"
L4 L5: library part SER29XX, "Inductor, open, TH"
L6 L7: "Inductor, Shielded E Core, Ferrite, 6.8uH, 30A, 0.00186 ohm, SMD"
L100 L200: library part SER2918H-332KL, "Inductor, Shielded E Core, Ferrite, 3.3uH, 28A, 0.0026 ohm, SMD"
Logo1: library part TI_Logo, "Texas Instrument Corporate Signature"
NT1 NT2: "Single point connection between nets."
Q1 Q2 Q3 Q4 Q5 Q6 Q7 Q8 Q9 Q10: "MOSFET, N-CH, 60V, 100A, SOT669"
Q11 Q12 Q13 Q14: library part IPB100N10S3-05, "MOSFET, N-CH, 40V, 120A, DDPAK"
Q15: library part "MMBT2222A, Fairchild Semiconductor", "Transistor, NPN, 40V, 0.15A, SOT-23"
R1 R2: "RES, 0.2 ohm, 1%, 2W, 2512"
R3: library part CSS2725FTL500, "RES, 0.001 ohm, 1%, 4W, RES_2725"
R4 R35: "RES, 49.9 ohm, 1%, 0.1W, 0603"
R5: "RES, 178k ohm, 1%, 0.1W, 0603"
R6: "RES, 53.6k ohm, 1%, 0.1W, 0603"
R7: "RES, 10.2k ohm, 1%, 0.1W, 0603"
R8: "RES, 88.7k ohm, 1%, 0.1W, 0603"
R9: "RES, 49.9k ohm, 1%, 0.1W, 0603"
R10: "RES, 237k ohm, 1%, 0.1W, 0603"
R11: "RES, 75.0k ohm, 1%, 0.1W, 0603"
R12: "RES, 1.00 ohm, 1%, 0.125W, 0805"
R13: "RES, 5.76k ohm, 1%, 0.1W, 0603"
R14 R15 R16 R17 R18 R19 R20 R21 R25 R26: "RES, 2.2 ohm, 5%, 0.1W, 0603"
R22 R24: "RES, 10 ohm, 5%, 0.25W, 1206"
R23 R36: "RES, 0 ohm, 5%, 0.1W, 0603"
R27 R28 R32 R34: "RES, 100 ohm, 1%, 0.1W, 0603"
R29 R30: library part CSRN2512FKR200, "RES, 0.001ohm, 1%, 2W, 2512"
R31 R33: "RES, 249k ohm, 1%, 0.1W, 0603"
R37 R38: "RES, 20.0k ohm, 1%, 0.1W, 0603"
R39: "TRIMMER, 10K, 0.25W, SMD"
R40: "RES, 1.62k ohm, 1%, 0.1W, 0603"
R41: "RES, 36.5k ohm, 1%, 0.1W, 0603"
R42: "RES, 3.01k ohm, 1%, 0.1W, 0603"
R43: "RES, 0.0005 ohm, 1%, 4W, RES_2725"
R44 R49 R52 R53: "RES, 10.0k ohm, 1%, 0.1W, 0603"
R45: "RES, 13.7k ohm, 1%, 0.1W, 0603"
R46 R47: "RES, 82.5k ohm, 1%, 0.1W, 0603"
R48: "RES, 1.00k ohm, 1%, 0.1W, 0603"
R50: "RES, 16.5k ohm, 1%, 0.1W, 0603"
R51: "RES, 11.0k ohm, 1%, 0.1W, 0603"
T1 T2: "Terminal 50A Lug"
T3 T4: "Terminal 90A Lug"
TP1 TP3 TP4 TP5 TP7 TP8 TP9 TP10 TP11 TP12: "Test Point, Multipurpose, Red, TH"
TP2 TP6: "Test Point, Multipurpose, Black, TH"
U1 U7: "CURRENT SHUNT MONITOR -16V to +80V Common-Mode Range, DBV0005A"
U2: "Buck Inverting Buck-Boost Step Down Regulator with 3.5 to 60 V Input and 0.8 to 58 V Output, -40 to 150 degC, 10-Pin MSOP-PowerPAD (DGQ), Green (RoHS & no Sb/Br)"
U3 U4 U5: "Single-Supply Centigrade Temperature Sensor, 3-pin SOT-23, Pb-Free"
U6: "LM5119/LM5119Q Wide Input Range Dual Synchronous Buck Controller, RTV0032A"
U8: "High-Side Protection Controller with Low Quiescent Current, 10-pin MSOP, Pb-Free"

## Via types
v1: diameter 32, hole 16, Top Layer to Bottom Layer, 172 vias
v2: diameter 19.68, hole 7.87, Top Layer to Bottom Layer, 10 vias
v3: diameter 34, hole 16, Top Layer to Bottom Layer, 8 vias
v4: diameter 200, hole 150, Top Layer to Bottom Layer, 5 vias

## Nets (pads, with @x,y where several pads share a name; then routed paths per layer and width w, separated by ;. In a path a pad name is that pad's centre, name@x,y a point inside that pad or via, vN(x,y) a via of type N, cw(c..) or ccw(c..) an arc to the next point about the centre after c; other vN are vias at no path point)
COMP: C48.1 R38.1 U6.10 U6.15
GND: C1.2 C2.2 C3.2 C4.2 C5.2 C6.2 C7.2 C8.2 C10.2 C11.2 C12.2 C13.2 C14.2 C15.2 C16.2 C17.2 C18.2 C19.2 C20.2 C21.2 C22.2 C23.2 C24.2 C25.2 C26.2 C27.2 C28.2 C29.2 C30.2 C34.2 C35.2 C36.2 C37.2 C39.2 C40.2 C41.1 C42.1 C45.2 C46.2 C47.2 C50.2 C51.2 C52.2 C53.2 D1.2 J1.2 J2.2 J3.2 J4.2 J5.2 NT1.2 NT2.1 R7.1 R9.1 R10.1 R13.1 R22.1 R24.1 R29.1 R30.1 R40.1 R41.1 R42.1 R44.1 R50.1 R51.1 T2.1 T4.1 TP2.1 TP6.1 U1.2 U2.9 U2.11 U3.3 U4.3 U5.3 U6.3 U6.12 U6.22 U6.33 U7.2 U8.6
  other v1: 125,135 170,135 215,135 260,135 580,135 625,135 125,180 170,180 215,180 625,180 125,225 170,225 125,270 170,270 125,315 170,315 125,360 170,360 125,405 170,405 215,405 625,405 125,450 170,450 215,450 260,450 580,450 625,450 4360,3080 4400,3080 4440,3080 4875,3085 4915,3085 4955,3085 4995,3085 4360,3120 4875,3125 4915,3125 4955,3125 4995,3125 4360,3160 4875,3165 4915,3165 4955,3165 4995,3165 4875,3205 4915,3205 4955,3205 4995,3205 4875,3245 4915,3245 4955,3245 4995,3245 4875,3285 4915,3285 4955,3285 4995,3285 4875,3335 4915,3335 4955,3335 4995,3335 4875,3375 4915,3375 4955,3375 4995,3375 4875,3415 4915,3415 4955,3415 4995,3415 4875,3455 4915,3455 4955,3455 4995,3455 4360,3460 4875,3495 4915,3495 4955,3495 4995,3495 4360,3500 4875,3535 4915,3535 4955,3535 4995,3535 4360,3540 4400,3540 4440,3540
  other v2: 2556.06,2326.06 2506.06,2376.06 2556.06,2376.06 2606.06,2376.06 2556.06,2426.06 1022.3,3486.35 1057.74,3486.35 1040.02,3509.97 1022.3,3533.59 1057.74,3533.59
  other v3: 796.88,74.36 964,75 796.88,134.36 963.12,134.36 962,192 796.88,194.36
NetC1_1: C1.1 L1.1 L100.1 R1.1 R3.2 U1.5 | length 274
  Top Layer w25: U1.5 897.41,771.18 R3.2
NetC2_1: C2.1 L1.2 L2.1 L100.2 L200.1 R1.2 R2.1
  other v3: 1140,170 1200,170
NetC9_1: C9.1 D1.1 L3.1 TP4.1 U2.10
NetC9_2: C9.2 U2.1
NetC10_1: C10.1 U2.4
NetC11_1: C11.1 R8.2
NetC12_1: C12.1 R8.1 U2.8
NetC14_1: C14.1 J2.1 U3.2
NetC16_1: C16.1 J3.1 U4.2
NetC18_1: C18.1 J4.1 U5.2
NetC28_1: C28.1 D2.2 U6.1
NetC29_1: C29.1 R12.2 U6.29
NetC31_1: C31.1 D2.1 U6.30
NetC31_2: C31.2 C38.1 L5.2 L7.1 Q2.1 Q2.2 Q2.3 Q4.1 Q4.2 Q4.3 Q6.1 Q6.2 Q6.3 Q7.5 Q9.5 R33.2 TP8.1 U6.32
NetC32_1: C32.1 D3.1 U6.27
NetC32_2: C32.2 C33.1 L4.1 L6.2 Q1.1 Q1.2 Q1.3 Q3.1 Q3.2 Q3.3 Q5.1 Q5.2 Q5.3 Q8.5 Q10.5 R31.2 TP7.1 U6.25
NetC33_2: C33.2 R22.2
NetC38_2: C38.2 R24.2
NetC41_2: C41.2 U6.18
NetC42_2: C42.2 U6.14
NetC43_1: C43.1 R27.1 U6.20
NetC43_2: C43.2 R34.1 U6.21
NetC44_1: C44.1 R28.1 U6.5
NetC44_2: C44.2 R32.1 U6.4
NetC45_1: C45.1 R31.1 U6.19
NetC46_1: C46.1 U6.7
NetC47_1: C47.1 R33.1 U6.6
NetC48_2: C48.2 C49.2 R37.1 R39.1 R39.2 R40.2 U6.9
NetC49_1: C49.1 R38.2
NetC50_1: C50.1 D4.3 Q15.1 R44.2
NetC52_1: C52.1 D5.3 U8.2
NetC53_1: C53.1 U8.7
NetD4_1: D4.1 Q11.3 Q12.3 Q13.3 Q14.3 Q15.2
NetD5_1: D5.1 Q11.4 Q13.4 R43.2 R45.2 R46.2 R47.2 U7.5
NetD6_1: D6.1 Q11.1 Q12.1 Q13.1 Q14.1 Q15.3 R48.1
NetD6_3: D6.3 R48.2 U8.10
NetJ1_1: J1.1 U1.1
NetJ5_1: J5.1 U7.1
NetNT1_1: NT1.1 R34.2
NetNT2_2: NT2.2 R32.2
NetQ1_4: Q1.4 R16.2
NetQ2_4: Q2.4 R17.1
NetQ3_4: Q3.4 R14.2
NetQ4_4: Q4.4 R15.1
NetQ5_4: Q5.4 R18.2
NetQ6_4: Q6.4 R19.1
NetQ7_1: Q7.1 Q7.2 Q7.3 Q9.1 Q9.2 Q9.3 R28.2 R30.2
NetQ7_4: Q7.4 R20.1
NetQ8_1: Q8.1 Q8.2 Q8.3 Q10.1 Q10.2 Q10.3 R27.2 R29.2
NetQ8_4: Q8.4 R21.2
NetQ9_4: Q9.4 R25.1
NetQ10_4: Q10.4 R26.2
NetQ12_4: Q12.4 Q14.4 R49.1 T3.1
  other v1: 4361.89,3775.55 4401.89,3775.55 4441.89,3775.55 4876.89,3780.55 4916.89,3780.55 4956.89,3780.55 4996.89,3780.55 4361.89,3815.55 4876.89,3820.55 4916.89,3820.55 4956.89,3820.55 4996.89,3820.55 4361.89,3855.55 4876.89,3860.55 4916.89,3860.55 4956.89,3860.55 4996.89,3860.55 4876.89,3900.55 4916.89,3900.55 4956.89,3900.55 4996.89,3900.55 4876.89,3940.55 4916.89,3940.55 4956.89,3940.55 4996.89,3940.55 4876.89,3980.55 4916.89,3980.55 4956.89,3980.55 4996.89,3980.55 4876.89,4030.55 4916.89,4030.55 4956.89,4030.55 4996.89,4030.55 4876.89,4070.55 4916.89,4070.55 4956.89,4070.55 4996.89,4070.55 4876.89,4110.55 4916.89,4110.55 4956.89,4110.55 4996.89,4110.55 4876.89,4150.55 4916.89,4150.55 4956.89,4150.55 4996.89,4150.55 4361.89,4155.55 4876.89,4190.55 4916.89,4190.55 4956.89,4190.55 4996.89,4190.55 4361.89,4195.55 4876.89,4230.55 4916.89,4230.55 4956.89,4230.55 4996.89,4230.55 4361.89,4235.55 4401.89,4235.55 4441.89,4235.55
NetR3_1: R3.1 T1.1 TP1.1 U1.4 | length 274
  Top Layer w25: R3.1 822.6,771.18 U1.4
  other v1: 125,605 170,605 215,605 260,605 580,605 625,605 125,650 170,650 215,650 625,650 125,695 170,695 125,740 170,740 125,785 170,785 125,830 170,830 125,875 170,875 215,875 625,875 125,920 170,920 215,920 260,920 580,920 625,920
NetR4_1: R4.1 R6.2 TP5.1
NetR5_1: R5.1 R9.2 U2.3
NetR6_1: R6.1 R7.2 U2.7
NetR10_2: R10.2 U2.5
NetR14_1: R14.1 R16.1 R18.1 U6.26
NetR15_2: R15.2 R17.2 R19.2 U6.31
NetR20_2: R20.2 R25.2 U6.2
NetR21_1: R21.1 R26.1 U6.23
NetR23_1: R23.1 U6.16
NetR35_1: R35.1 R37.2 TP10.1
NetR36_2: R36.2 U6.17
NetR39_3: R39.3 R42.2
NetR41_2: R41.2 U6.13
NetR45_1: R45.1 U8.1
NetR46_1: R46.1 R50.2 U8.4
NetR47_1: R47.1 R51.2 U8.3
NetR49_2: R49.2 U8.9
NetR52_2: R52.2 TP11.1 U8.8
NetR53_2: R53.2 TP12.1 U8.5
UVLO: C27.1 R11.1 R13.2 U6.28
VCC2: C30.1 D3.2 R23.2 R36.1 U6.24
VCC_5V: C4.1 C7.1 C8.1 C13.1 C15.1 C17.1 C51.1 L3.2 R4.2 R52.1 R53.1 TP3.1 U1.3 U3.1 U4.1 U5.1 U7.3
VIN: C3.1 C5.1 C6.1 C19.1 C20.1 C21.1 C22.1 C23.1 C24.1 C25.1 C26.1 L2.2 L200.2 Q1.5 Q2.5 Q3.5 Q4.5 Q5.5 Q6.5 R2.2 R5.2 R11.2 R12.1 U2.2
VOUT: C34.1 C35.1 C36.1 C37.1 C39.1 C40.1 L4.2 L5.1 L6.1 L7.2 R35.2 R43.1 TP9.1 U7.4
pads on no net: D4.2 D5.2 D6.2 L1.3 L2.3 L4.3 L5.3 L6.3 L7.3 L100.3 L200.3 U2.6 U6.8 U6.11
copper on no net:
  other v4: 410,1360 4800,1360 2680,1900 1240,4510 4140,4510

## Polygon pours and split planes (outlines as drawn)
NetC2_1 on Top Layer "Top Layer-No Net 2" (solid, pour order 6): 1093.23,190 1093.23,78.43 1246.77,78.43 1246.77,190
NetC1_1 on Top Layer "Top Layer-No Net 1" (solid, pour order 4): 890,851.89 890,340 900,330 950,330 980,330 1070,240 1270,240 1290,220 1290,0 1830,0 1830,550 1830,830 1810,850 1808.11,851.89 960,851.89 900,851.89
NetR3_1 on Top Layer "Top Layer-No Net" (solid, pour order 2): 100,950 830,950 830,570 450,570 100,570

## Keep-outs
Keep-Out Layer:
  lines w5: -2.5,0 ccw(c0,0) 0,-2.5 ; -2.5,0 ccw(c0,0) 0,-2.5 ; -2.5,0 -2.5,4724.41 ; -2.5,4724.41 cw(c0,4724.41) 0,4726.91 ; -2.5,4724.41 cw(c0,4724.41) 0,4726.91 ; 0,-2.5 5118.11,-2.5 ; 0,4726.91 5118.11,4726.91 ; 5118.11,-2.5 ccw(c5118.11,0) 5120.61,0 ; 5118.11,-2.5 ccw(c5118.11,0) 5120.61,0 ; 5118.11,4726.91 cw(c5118.11,4724.41) 5120.61,4724.41 ; 5118.11,4726.91 cw(c5118.11,4724.41) 5120.61,4724.41 ; 5120.61,0 5120.61,4724.41
  lines w7.01: 0,0 0,4724.41 5118.11,4724.41 5118.11,0 0,0
  text ".Layer_Name" at 577,-858.49 h60

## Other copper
Top Layer:
  text ".Layer_Name" at 577,-858.49 h60
Bottom Layer:
  text ".Layer_Name" at 577,-858.49 h60

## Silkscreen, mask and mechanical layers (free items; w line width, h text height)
Top Overlay:
  text ".PRJ_Number" at 4300,830 h60
  text ".PCB_Rev" at 4890,830 h60
  text ".Layer_Name" at 577,-858.49 h60
Bottom Overlay:
  text ".Layer_Name" at 577,-858.49 h60
Top Paste:
  text ".Layer_Name" at 577,-858.49 h60
Bottom Paste:
  text ".Layer_Name" at 577,-858.49 h60
Top Solder:
  text ".Layer_Name" at 577,-858.49 h60
  text ".Layer_Name" at 577,-858.49 h60
Bottom Solder:
  text ".Layer_Name" at 577,-858.49 h60
Drill Guide:
  text ".Layer_Name" at 577,-858.49 h60
M1 Board Outline:
  the board outline again, w7.01
  text ".Layer_Name" at 577,-858.49 h60
M2 Board Dimensions:
  rectangle: 124.5,-410.5 499.5,-285.5
  rectangle: -0.5,-285.5 124.5,-160.5
  lines w7: -0.5,-285.5 999.5,-285.5 ; 124.5,-410.5 124.5,-160.5 ; 249.5,-410.5 249.5,-160.5 ; 499.5,-410.5 499.5,-160.5 ; 749.5,-410.5 749.5,-160.5 ; -0.5,-410.5 -0.5,-160.5 999.5,-160.5 999.5,-410.5 -0.5,-410.5
  lines w10: -0.5,-475.5 -0.5,-455.5 ; 59.5,-485.5 -0.5,-465.5 ; 59.5,-445.5 -0.5,-465.5 ; 223.58,-465.5 -0.5,-465.5 ; 775.42,-465.5 999.5,-465.5 ; 939.5,-485.5 999.5,-465.5 ; 939.5,-445.5 999.5,-465.5 ; 999.5,-475.5 999.5,-455.5
  text "1000 (mil)" at 233.58,-501.49 h60
  text ".Layer_Name" at 577,-858.49 h60
M3 3D STEP Top:
  text ".Layer_Name" at 577,-858.49 h60
M4 3D STEP Bottom:
  text ".Layer_Name" at 577,-858.49 h60
M5 Assembly Top:
  lines w10: -292,-930.17 6308,-930.17 ; -292,-726.83 6310,-726.83 ; -292,-523.5 -292,-1133.5 3713,-1133.5 6310,-1133.5 6310,-523.5 -291.5,-523.5 -291.5,-1133.5 1284,-1133.5 ; 2173,-1133.5 2173,-523.5 ; 3440,-726.83 3440,-523.5 ; 4280,-726.83 4280,-523.5 ; 4902,-1140 4902,-937.17
  text "COMPONENTS MARKED 'DNP' SHOULD NOT BE POPULATED." at 1153.5,-318.5 h60
  text "ASSEMBLY VARIANT:" at 1153,-434 h60
  text ".VariantName" at 2189,-434 h60
  text "PCB VIEWED FROM TOP SIDE" at -228.5,-655.67 h60
  text "BOARD #:" at 2248,-655.67 h60
  text ".PRJ_Number" at 2793.5,-655.67 h60
  text "REV:" at 3638,-655.67 h60
  text ".PCB_Rev" at 3929.5,-655.67 h60
  text "SVN REV:" at 4476,-655.67 h60
  text ".VersionControl_RevNumber" at 4982,-655.67 h60
  text "IGNORE ->" at -228.5,-858.49 h60
  text "PLOT NAME =" at -228.5,-1064.34 h60
  text ".plot_File_Name" at 577,-1064.34 h60
  text "GENERATED    :" at 2250,-1064.34 h60
  text ".Print_Date" at 3119.5,-1064.34 h60
  text ".Print_Time" at 3848.5,-1064.34 h60
  text "TEXAS INSTRUMENTS" at 5113,-1064.34 h60
M6 Assembly Bottom:
  lines w10: -292.5,-727.33 6309.5,-727.33 ; -290.5,-930.67 6309.5,-930.67 ; 1115.5,-1140.5 1115.5,-937.67 ; 1737.5,-727.33 1737.5,-524 ; 2577.5,-727.33 2577.5,-524 ; 3844.5,-1134 3844.5,-524 ; 4733.5,-1134 6309,-1134 6309,-524 -292.5,-524 -292.5,-1134 2304.5,-1134 6309.5,-1134 6309.5,-524
  text "COMPONENTS MARKED 'DNP' SHOULD NOT BE POPULATED." at 6102,-318 h60
  text ".VariantName" at 5058,-434 h60
  text "ASSEMBLY VARIANT:" at 6097,-434 h60
  text ".VersionControl_RevNumber" at 1035.5,-656.17 h60
  text "SVN REV:" at 1541.5,-656.17 h60
  text ".PCB_Rev" at 2088,-656.17 h60
  text "REV:" at 2379.5,-656.17 h60
  text ".PRJ_Number" at 3224,-656.17 h60
  text "BOARD #:" at 3769.5,-656.17 h60
  text "PCB VIEWED FROM BOTTOM SIDE" at 6246,-656.17 h60
  text "IGNORE ->" at 2547.85,-858.49 h60
  text "TEXAS INSTRUMENTS" at 904.5,-1064.84 h60
  text ".Print_Time" at 2169,-1064.84 h60
  text ".Print_Date" at 2898,-1064.84 h60
  text "GENERATED    :" at 3767.5,-1064.84 h60
  text ".plot_File_Name" at 5440.5,-1064.84 h60
  text "PLOT NAME =" at 6246,-1064.84 h60
M9 Title Sheet:
  drawing of 57 lines, arcs and shapes, not listed
  text "1" at 739.84,8036.5 h70
  text "2" at 3235.5,8036.5 h70
  text "3" at 5724.84,8036.5 h70
  text "4" at 8231.51,8036.5 h70
  text "5" at 10730.5,8036.5 h70
  text "6" at 13235.5,8036.5 h70
  text "A" at -416.5,6893.5 h70
  text "A" at 14383.5,6893.5 h70
  text "B" at -416.5,4513.5 h70
  text "B" at 14383.5,4513.5 h70
  text "C" at -416.5,2138.5 h70
  text "C" at 15285.5,1822.5 h70
  text "PROJECT TITLE:" at 11343.5,277.5 h45
  text ".PRJ_Title" at 11393.5,144.17 h70
  text "DESIGNED FOR:" at 11343.5,-23.5 h45
  text ".PRJ_Customer" at 11393.5,-163.5 h70
  text "D" at -416.5,-231.5 h70
  text "D" at 14383.5,-231.5 h70
  text "FILE NAME:" at 11343.5,-323.5 h45
  text ".PCB_File_Name_No_Path" at 11393.5,-443.5 h70
  text "Texas Instruments (TI) and/or its licensors do not warrant the accuracy or completeness of this specification" at 6374,-605.34 h45
  text "ENGINEER:" at 11343.5,-613.5 h45
  text "LAYOUT BY:" at 12848.5,-613.5 h45
  text "or any information contained therein. TI and/or its licensors do not warrant that this design will meet" at 6329.01,-718 h45
  text ".PRJ_Engineer" at 11393.5,-768.49 h70
  text ".PCB_Layout" at 12899,-768.49 h70
  text "the specifications, will be suitable for your application or fit for any particular purpose, or will operate in" at 6329.01,-830.67 h45
  text ".Layer_Name" at 577,-858.49 h60
  text "ALTIUM DESIGNER VERSION:" at 12848.5,-923.5 h45
  text "an implementation. TI and/or its licensors do not warrant that the design is production worthy. You should" at 6329.01,-943.33 h45
  text "completely validate and test your design implementation to confirm the system functionality for your application." at 6374,-1056 h45
  text ".print_Scale" at 11393.5,-1056.83 h70
  text ".Application_BuildNumber" at 12899,-1056.83 h70
  text "1" at 739.84,-1263.5 h70
  text "2" at 3235.5,-1263.5 h70
  text "3" at 5724.84,-1263.5 h70
  text "4" at 8231.51,-1263.5 h70
  text "5" at 10730.5,-1263.5 h70
  text "6" at 13235.5,-1263.5 h70
M10 Fab Notes:
  drawing of 212 lines, arcs and shapes, not listed
  text "DESIGN INFORMATION" at 12381.02,6810 h60
  text "(REFER ALSO ARRAY/PANEL PROFILING INFORMATION)" at 12019.46,6648.29 h60
  text "BOARD SIZE" at 11333.46,6644 h60
  text "3450MIL" at 11795.78,6516.18 h60
  text "X" at 12301.46,6516.18 h60
  text "4950MIL" at 12532.78,6516.18 h60
  text "Number of Layers :" at 11736.46,6319 h60
  text "2" at 12831.27,6309 h60
  text "MIN. TRACK WIDTH:" at 11736.46,6180 h60
  text "8" at 12832.7,6180 h60
  text "MIL" at 12987.46,6180 h60
  text "MIN. CLEARANCE:" at 11736.46,6048 h60
  text "8" at 12832.7,6048 h60
  text "MIL" at 12987.46,6048 h60
  text "MIN. VIA PAD SIZE:" at 11736.46,5916 h60
  text "24" at 12802.71,5916 h60
  text "MIL" at 12987.46,5916 h60
  text "0.05mm (2MIL)" at 12431.46,5774.29 h60
  text "MINIMUM ANNULAR RING" at 11407.23,5770 h60
  text "EXTERNAL" at 13139.46,5770 h60
  text "PER" at 11607.23,5652 h60
  text "IPC-D-275 CLASS 2 LEVEL C" at 11827.23,5652 h60
  text "MIL, HOLES" at 13315.46,5539.71 h60
  text "+/-" at 12923,5539 h60
  text "+/-" at 13777,5539 h60
  text "REGISTRATION TOLERANCES:" at 11407.23,5534 h60
  text "METAL" at 12607,5534 h60
  text "5" at 13183.2,5534 h60
  text "3" at 14016.2,5534 h60
  text "MIL" at 14132.46,5534 h60
  text "MATERIAL:" at 11332.46,5324.54 h60
  text "FR-4 High Tg" at 12318.9,5184.21 h60
  text "FR-408" at 11753.46,5175.64 h60
  text "X" at 12165.46,5175.64 h60
  text "OTHER" at 13241.46,5175.64 h60
  text "62 MIL (1.6mm) +/-10%" at 12073.56,5012.92 h60
  text "THICKNESS:" at 11407.23,5008.64 h60
  text "X" at 11945.4,5008.64 h60
  text "OTHER" at 13358.46,5008.64 h60
  text "TOLERANCE:" at 11407.23,4850.64 h60
  text "X" at 12246.53,4850.64 h60
  text "ANSI IPC-6012 TYPE 3 CLASS 2" at 12433.48,4850.64 h60
  text "OTHER +/-" at 12433.46,4694.64 h60
  text "BOW & TWIST:" at 11407.23,4537.64 h60
  text "X" at 12246.53,4537.64 h60
  text "ANSI IPC-6012 TYPE 3 CLASS 2" at 12433.48,4537.64 h60
  text "OTHER +/-" at 12433.46,4379.13 h60
  text "COPPER THICKNESS (FINISHED):" at 11332.46,4243.64 h60
  text "1.4MIL (1oz)" at 12212.46,4090.92 h60
  text "2MIL (1.4oz)" at 12979.46,4090.92 h60
  text "2.8MIL (2oz)" at 13706.46,4090.92 h60
  text "OUTER:" at 11689.46,4086.64 h60
  text "X" at 12084,4086 h60
  text "1.4MIL (1oz)" at 12212.46,3933.92 h60
  text "2.8MIL (2oz)" at 12979.46,3933.92 h60
  text "N/A" at 13706,3934.29 h60
  text "INNER SIGNAL:" at 11400.38,3929.64 h60
  text "X" at 12085.42,3929.64 h60
  text "DRILLING:" at 12234.46,3474.64 h60
  text "REFERENCE:" at 12309.23,3357.64 h60
  text "X" at 12957.46,3357.64 h60
  text "AS SHOWN" at 13144.46,3357.64 h60
  text "X" at 13858.46,3357.64 h60
  text "NC_DRILL FILES" at 13995.46,3357.64 h60
  text "PTH MIN COPPER THICKNESS:" at 12309.23,3199.64 h60
  text "X" at 13659.46,3199.64 h60
  text "1MIL" at 13796.46,3199.64 h60
  text "OTHER" at 14293.46,3199.64 h60
  text "BOARD FINISH:" at 12234.46,3040.64 h60
  text "SILKSCREEN:" at 12389.68,2922.64 h60
  text "X" at 13338.46,2922.64 h60
  text "TOP" at 13464.46,2922.64 h60
  text "X" at 13848.46,2922.64 h60
  text "BOTTOM" at 13975.46,2922.64 h60
  text "SILKSCREEN COLOR:" at 12389.68,2755.64 h60
  text "X" at 13337.42,2755.64 h60
  text "WHITE" at 13464.46,2755.64 h60
  text "OTHER" at 13975.46,2755.64 h60
  text "SOLDER RESIST COLOR:" at 12389.68,2585.64 h60
  text "X" at 12957.42,2426.44 h60
  text "GREEN" at 13084.46,2426.44 h60
  text "BLUE" at 13675.46,2426.44 h60
  text "OTHER" at 14213.46,2426.44 h60
  text "IMMERSION GOLD (ENIG)" at 13295.46,2237.92 h60
  text "ENEPIG" at 14633,2234.64 h60
  text "SURFACE FINISH:" at 12234.46,2233.64 h60
  text "X" at 13108.51,2233.64 h60
  text "IMM. TIN/SILVER OR EQUIV" at 12564,2076.64 h60
  text "OTHER" at 13995.46,2076.64 h60
  text "N.C. ROUTE" at 12393.46,2057.64 h60
  text "X" at 13072.46,2057.64 h60
  text "V. SCORE" at 13259.46,2057.64 h60
  text "CERTIFICATION:" at 11332.46,1920.64 h60
  text "MATERIALS AND WORKMANSHIP FOR ALL PCBS" at 12057.46,1920.64 h60
  text "ARRAY/PANEL:" at 12234.46,1897.64 h60
  text "CUT AND TRIM PER MECH LAYER 1" at 13295.46,1893.35 h60
  text "TO MEET OR EXCEED THE REQUIREMENTS OF:" at 12057.46,1822.64 h60
  text "X" at 11683.96,1686.13 h60
  text "ANSI IPC-A-600F CLASS ->" at 11822.96,1686.13 h60
  text "X" at 13462.02,1686.13 h60
  text "2" at 13580.96,1686.14 h60
  text "1" at 13265.96,1684.64 h60
  text "3" at 13934.96,1684.64 h60
  text "X" at 11686.02,1526.64 h60
  text "UL 94V-0" at 11822.96,1526.64 h60
  text "X" at 12498.02,1526.64 h60
  text "RoHS" at 12634.96,1526.64 h60
  text "OTHER" at 13279.36,1526.64 h60
  text "PER ORDER" at 13676.42,1526.64 h60
  text "ADDITIONAL REQUIREMENTS:" at 11332.46,1385.64 h60
  text "MICROSECTION:" at 11407.23,1270.64 h60
  text "YES" at 12312.96,1270.64 h60
  text "REQUIRED" at 13174.46,1114.49 h60
  text "BARE BOARD ELEC. TEST:" at 11407.23,1111.64 h60
  text "NONE" at 12712.96,1111.64 h60
  text "X" at 13047.46,1111.64 h60
  text "PER ORDER" at 13766.46,1111.64 h60
  text "MANUFACTURER'S UL:" at 11407.23,954.64 h60
  text "RAIL" at 12572.96,950.35 h60
  text "METAL" at 13064.77,950.35 h60
  text "X" at 13440,950 h60
  text "SILK" at 13576.46,950.35 h60
  text ".Layer_Name" at 577,-858.49 h60
M11 Gerber Information:
  lines w10: -292,-930.17 6308,-930.17 ; -292,-726.83 6310,-726.83 ; -292,-523.5 -292,-1133.5 3713,-1133.5 6310,-1133.5 6310,-523.5 -291.5,-523.5 -291.5,-1133.5 1284,-1133.5 ; 2173,-1133.5 2173,-523.5 ; 3440,-726.83 3440,-523.5 ; 4280,-726.83 4280,-523.5 ; 4902,-1140 4902,-937.17
  text "ALL ARTWORK VIEWED FROM TOP SIDE" at -228.5,-655.67 h60
  text "BOARD #:" at 2248,-655.67 h60
  text ".PRJ_Number" at 2793.5,-655.67 h60
  text "REV:" at 3638,-655.67 h60
  text ".PCB_Rev" at 3929.5,-655.67 h60
  text "SVN REV:" at 4476,-655.67 h60
  text ".VersionControl_RevNumber" at 4982,-655.67 h60
  text "LAYER NAME =" at -228.5,-858.49 h60
  text "PLOT NAME =" at -228.5,-1064.34 h60
  text ".plot_File_Name" at 577,-1064.34 h60
  text "GENERATED    :" at 2250,-1064.34 h60
  text ".Print_Date" at 3119.5,-1064.34 h60
  text ".Print_Time" at 3848.5,-1064.34 h60
  text "TEXAS INSTRUMENTS" at 5113,-1064.34 h60
M12 Stackup:
  lines w6: 11360,7690.5 14220,7690.5 ; 11360,7803.1 14220,7803.1 ; 11300,6966 ccw(c11336,6966) 11336,6930 14244,6930 ccw(c14244,6966) 14280,6966 14280,7904 ccw(c14244,7904) 14244,7940 11336,7940 ccw(c11336,7904) 11300,7904 11300,6966
  text "Layer Stack Up Detail for: PMP10260 REVA.PcbDoc" at 11360,7832.95 h52
  text "Layer" at 11360,7761.1 h26
  text "Gerber" at 12361.14,7761.1 h26
  text "Copper" at 13016.52,7761.1 h26
  text "Dielectric" at 13714.35,7761.1 h26
  text "Name" at 11360,7709.1 h26
  text "Document" at 12361.14,7709.1 h26
  text "Thickness" at 13016.52,7709.1 h26
  text "Material" at 13714.35,7709.1 h26
  text "Top Solder Mask" at 11360,7634.9 h36
  text "(.GTS)" at 12361.14,7634.9 h36
  text "Solder Resist" at 13714.35,7634.9 h36
  text "Top Layer" at 11360,7529.69 h36
  text "(.GTL)" at 12361.14,7529.69 h36
  text "2.8mil" at 13016.52,7529.69 h36
  text "FR-4" at 13714.35,7477.08 h36
  text "MidLayer1" at 11360,7424.48 h36
  text "(.G1)" at 12361.14,7424.48 h36
  text "2.8mil" at 13016.52,7424.48 h36
  text "FR-4" at 13714.35,7371.88 h36
  text "MidLayer2" at 11360,7319.27 h36
  text "(.G2)" at 12361.14,7319.27 h36
  text "2.8mil" at 13016.52,7319.27 h36
  text "FR-4" at 13714.35,7266.67 h36
  text "Bottom Layer" at 11360,7214.06 h36
  text "(.GBL)" at 12361.14,7214.06 h36
  text "2.8mil" at 13016.52,7214.06 h36
  text "Bottom Solder Mask" at 11360,7108.85 h36
  text "(.GBS)" at 12361.14,7108.85 h36
  text "Solder Resist" at 13714.35,7108.85 h36
  text ".Layer_Name" at 577,-858.49 h60
M13 Component Bodies Top:
  text ".Layer_Name" at 577,-858.49 h60
M14 Component Bodies Bottom:
  text ".Layer_Name" at 577,-858.49 h60
M15 Courtyards Top:
  text ".Layer_Name" at 577,-858.49 h60
M16 Courtyards Bottom:
  text ".Layer_Name" at 577,-858.49 h60
Drill Drawing:
  text "Drill Table" at 5930,60 h60
  text ".Layer_Name" at 577,-858.49 h60

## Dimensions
0,0 to 5118.11,0 on M2 Board Dimensions
0,0 to 0,4724.41 on M2 Board Dimensions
